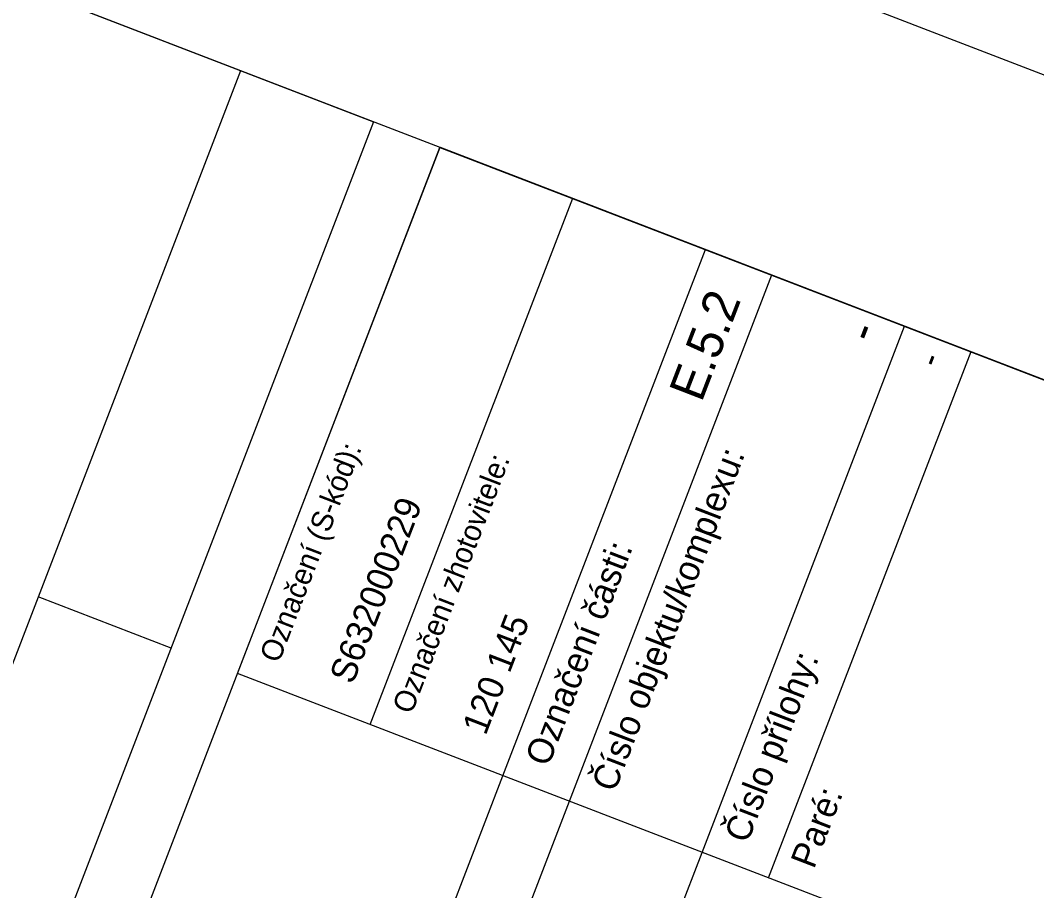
# Model space of a CAD drawing. Extents: x -755061 to -754557, y -1162352 to -1161657.
# Drawn here: x -754684.5 to -754613.1, y -1161799.7 to -1161738.5 of the extents above; entities that cross this region are included whole.
import ezdxf

# ---------------------------------------------------------------- set-up
doc = ezdxf.new("R2010")
doc.units = 0
doc.layers.add('ADJ_Formát', color=7, linetype='Continuous')

msp = doc.modelspace()

# ---------------------------------------------------------------- linework, layer by layer
at = {"layer": 'ADJ_Formát'}
for p, q in [((-754730.056, -1161900.651), (-754668.997, -1161741.995)), ((-754659.907, -1161787.979), (-754645.665, -1161750.974)), ((-754650.574, -1161791.57), (-754636.333, -1161754.566)), ((-754645.907, -1161793.366), (-754631.666, -1161756.362)), ((-754636.575, -1161796.958), (-754622.334, -1161759.954)), ((-754631.908, -1161798.754), (-754617.667, -1161761.749)), ((-754673.906, -1161782.591), (-754683.238, -1161778.999)), ((-754697.392, -1161913.222), (-754650.574, -1161791.57)), ((-754692.725, -1161915.018), (-754645.907, -1161793.366)), ((-754683.393, -1161918.61), (-754636.575, -1161796.958))]:
    msp.add_line(p, q, dxfattribs=at)
msp.add_lwpolyline([(-754909.895, -1161852.87), (-754834.469, -1161656.883), (-754557.287, -1161763.557), (-754632.713, -1161959.544)], dxfattribs=at)
for points in [[(-754884.046, -1161841.388), (-754822.987, -1161682.732), (-754580.336, -1161776.116), (-754641.396, -1161934.773)], [(-754767.387, -1161886.284), (-754706.328, -1161727.628), (-754659.664, -1161745.587), (-754720.724, -1161904.243)], [(-754589.669, -1161772.525), (-754603.91, -1161809.529), (-754669.239, -1161784.387), (-754654.998, -1161747.383)], [(-754716.062, -1161906.051), (-754655.003, -1161747.395), (-754589.674, -1161772.537), (-754650.733, -1161931.193)]]:
    msp.add_lwpolyline(points, close=True, dxfattribs=at)

# ---------------------------------------------------------------- texts
for s, height, rotation, p in [('E.5.2', 2.5, 68.9507, (-754636.616, -1161765.378)), ('-', 2.5, 68.95068, (-754624.467, -1161761.257)), ('-', 1.8, 68.95068, (-754619.937, -1161762.975)), ('Označení (S-kód):', 1.5, 68.95068, (-754666.326, -1161783.713)), ('Číslo objektu/komplexu:', 1.8, 68.95068, (-754642.715, -1161792.8)), ('Označení zhotovitele:', 1.5, 68.95068, (-754656.994, -1161787.305)), ('S632000229', 1.8, 68.95068, (-754661.129, -1161785.208)), ('Označení části:', 1.8, 68.95068, (-754647.381, -1161791.004)), ('120 145', 1.8, 68.95068, (-754651.796, -1161788.799)), ('Číslo přílohy:', 1.8, 68.95068, (-754633.382, -1161796.392)), ('Paré:', 1.8, 68.95068, (-754628.715, -1161798.188))]:
    msp.add_text(s, height=height, rotation=rotation, dxfattribs=at).set_placement(p)

doc.saveas('drawing.dxf')
